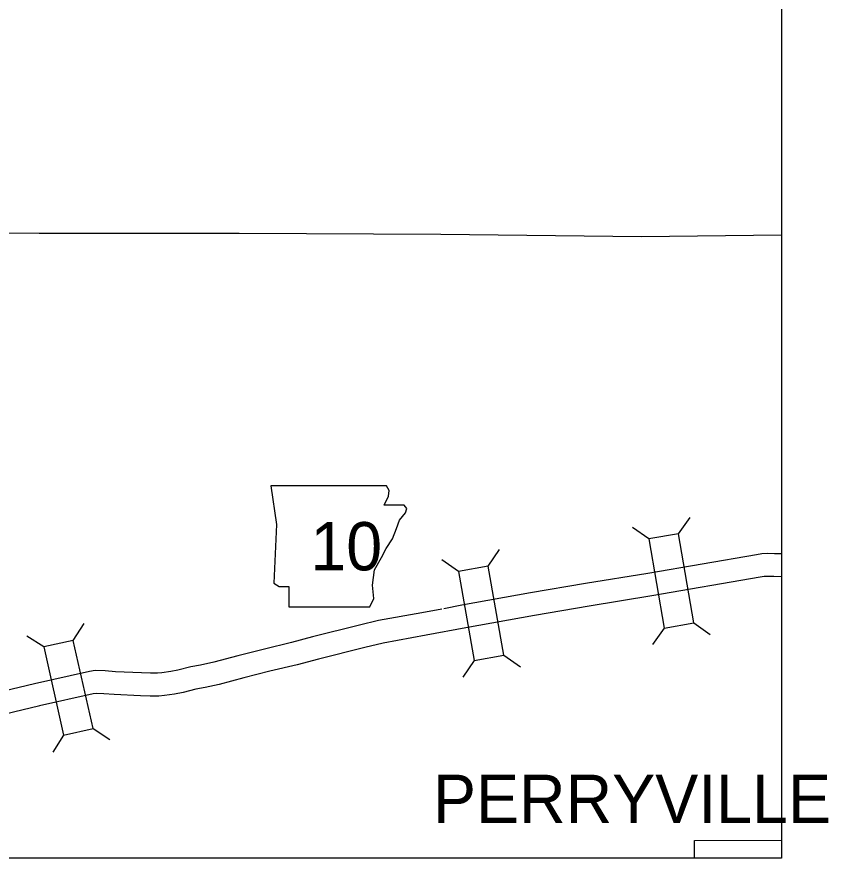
# Model space of a CAD drawing. Extents: x 1374139 to 1377472, y 1168351 to 1170484.
# Drawn here: x 1374928.1 to 1375034.7, y 1169604.3 to 1169714.8 of the extents above; entities that cross this region are included whole.
import ezdxf

# ---------------------------------------------------------------- set-up
doc = ezdxf.new("R2010")
doc.units = 0
doc.layers.add('26', color=7, linetype='Continuous')
doc.layers.add('Default', color=7, linetype='Continuous')

msp = doc.modelspace()

# ---------------------------------------------------------------- linework, layer by layer
at = {"layer": '26'}
msp.add_lwpolyline([(1374299.15, 1170388.77), (1375028.55, 1170388.77), (1375028.55, 1169604.28), (1374299.15, 1169604.28)], close=True, dxfattribs=at)
at = {"layer": 'Default'}
for p, q in [((1375015.05, 1169646.88), (1375016.58, 1169649.04)), ((1375011.15, 1169646.21), (1375008.99, 1169647.73)), ((1374990.04, 1169642.63), (1374991.54, 1169644.8)), ((1374986.14, 1169641.94), (1374983.97, 1169643.45)), ((1374935.54, 1169632.89), (1374936.96, 1169635.12)), ((1375013.16, 1169634.5), (1375011.64, 1169632.35)), ((1375017.07, 1169635.17), (1375019.22, 1169633.65)), ((1374931.68, 1169632.03), (1374929.45, 1169633.44)), ((1374992.12, 1169630.94), (1374994.29, 1169629.43)), ((1374988.22, 1169630.24), (1374986.71, 1169628.07)), ((1374938.14, 1169621.3), (1374940.37, 1169619.89)), ((1374934.28, 1169620.43), (1374932.86, 1169618.2)), ((1375017.15, 1169604.28), (1375017.12, 1169606.59)), ((1375017.12, 1169606.59), (1375017.17, 1169606.59)), ((1375017.17, 1169606.59), (1375028.55, 1169606.63)), ((1375028.55, 1169606.63), (1375028.55, 1169604.28)), ((1375028.55, 1169604.28), (1375017.15, 1169604.28))]:
    msp.add_line(p, q, dxfattribs=at)
for points in [[(1374931.08, 1169686.32), (1374904.76, 1169686.49), (1374878.41, 1169686.14), (1374852.12, 1169686.23), (1374825.63, 1169686.17), (1374798.95, 1169686.44), (1374798.96, 1169685.42), (1374786.98, 1169685.41)], [(1375028.55, 1169686.12), (1375010.18, 1169685.87), (1374983.83, 1169686.2), (1374957.33, 1169686.3), (1374931.08, 1169686.32)], [(1375028.55, 1169644.23), (1375027.67, 1169644.27), (1375026.78, 1169644.28), (1375025.99, 1169644.25), (1375025.29, 1169644.14), (1375011.03, 1169641.68), (1375002.82, 1169640.36), (1374995.59, 1169639.11), (1374986.57, 1169637.5), (1374984.2, 1169637.05)], [(1375028.55, 1169641.22), (1375027.58, 1169641.27), (1375026.82, 1169641.28), (1375026.29, 1169641.26), (1375025.78, 1169641.18), (1375011.52, 1169638.73), (1375003.31, 1169637.4), (1374996.11, 1169636.16), (1374987.11, 1169634.55), (1374981.9, 1169633.55), (1374976.26, 1169632.54), (1374973.84, 1169631.97), (1374967.74, 1169630.44), (1374964.94, 1169629.69), (1374961.38, 1169628.83), (1374957.93, 1169627.96), (1374954.73, 1169627.11), (1374952.86, 1169626.71), (1374951.63, 1169626.48), (1374949.96, 1169626.05), (1374948.86, 1169625.84), (1374947.55, 1169625.66), (1374946.79, 1169625.57), (1374945.65, 1169625.56), (1374944.36, 1169625.61), (1374940.9, 1169625.77), (1374939.56, 1169625.87), (1374938.56, 1169625.9), (1374938.18, 1169625.86), (1374931.11, 1169624.28)], [(1374983.96, 1169637), (1374981.35, 1169636.5), (1374975.65, 1169635.48), (1374973.13, 1169634.89), (1374966.98, 1169633.35), (1374964.19, 1169632.6), (1374960.66, 1169631.74), (1374957.18, 1169630.87), (1374954.03, 1169630.03), (1374952.27, 1169629.65), (1374950.98, 1169629.41), (1374949.3, 1169628.98), (1374948.37, 1169628.8), (1374947.17, 1169628.63), (1374946.61, 1169628.57), (1374945.7, 1169628.56), (1374944.49, 1169628.61), (1374941.09, 1169628.76), (1374939.72, 1169628.87), (1374938.43, 1169628.91), (1374937.68, 1169628.82), (1374930.46, 1169627.2)], [(1374930.44, 1169627.2), (1374915.58, 1169623.64)], [(1374931.14, 1169624.28), (1374916.19, 1169620.7)]]:
    msp.add_lwpolyline(points, dxfattribs=at)
for points in [[(1374961.49, 1169653.17), (1374962.25, 1169648.09), (1374961.91, 1169640.4), (1374962.59, 1169639.97), (1374963.86, 1169639.97), (1374963.86, 1169637.27), (1374974.52, 1169637.27), (1374975.02, 1169638.37), (1374974.86, 1169640.14), (1374975.11, 1169642.17), (1374976.04, 1169643.78), (1374976.63, 1169644.96), (1374977.48, 1169646.23), (1374977.99, 1169647.59), (1374978.41, 1169648.69), (1374979.17, 1169649.62), (1374979.34, 1169650.21), (1374979, 1169650.63), (1374976.38, 1169650.63), (1374976.97, 1169651.82), (1374977.05, 1169652.58), (1374976.7, 1169653.16)], [(1375017.07, 1169635.17), (1375015.05, 1169646.88), (1375011.15, 1169646.21), (1375013.16, 1169634.5)], [(1374992.12, 1169630.94), (1374990.04, 1169642.63), (1374986.14, 1169641.94), (1374988.22, 1169630.24)], [(1374931.68, 1169632.03), (1374934.28, 1169620.43), (1374938.14, 1169621.3), (1374935.54, 1169632.89)]]:
    msp.add_lwpolyline(points, close=True, dxfattribs=at)

# ---------------------------------------------------------------- texts
for s, p in [('10', (1374966.69, 1169642.08)), ('PERRYVILLE', (1374982.79, 1169608.91))]:
    msp.add_text(s, height=6.336, dxfattribs=at).set_placement(p)

doc.saveas('drawing.dxf')
